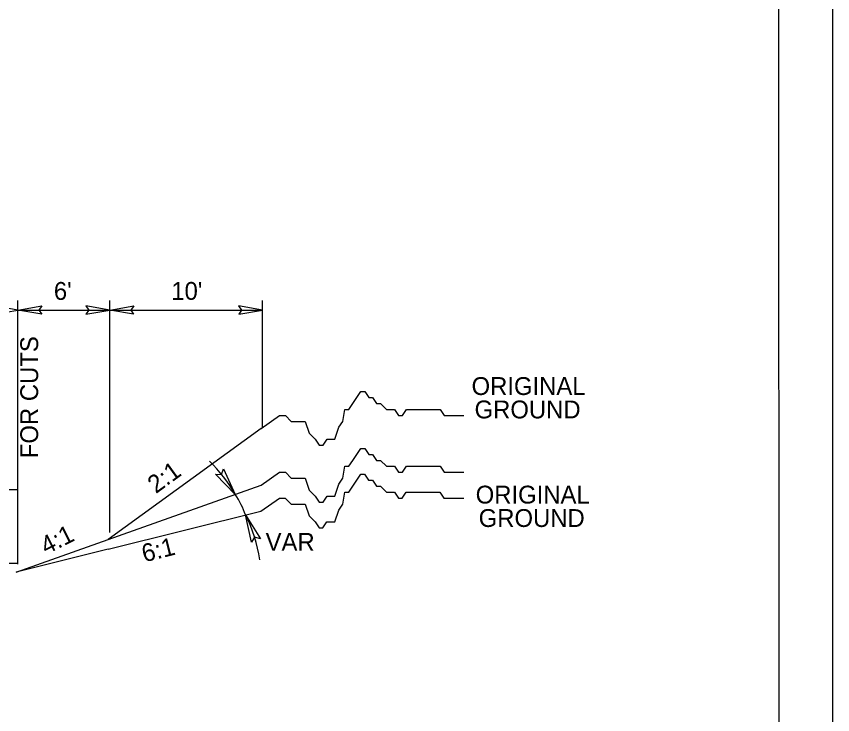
# Model space of a CAD drawing. Extents: x 1725232 to 1728895, y 538685 to 540544.
# Drawn here: x 1725504.7 to 1725568.8, y 539405 to 539459.8 of the extents above; entities that cross this region are included whole.
import ezdxf

# ---------------------------------------------------------------- set-up
doc = ezdxf.new("R2010")
doc.units = 0
for name, color, linetype in [('Default', 7, 'Continuous'), ('Overhead Sheet Border', 7, 'Continuous'), ('Prop Dimension Text', 7, 'Continuous'), ('Scratch_Level_0', 7, 'Continuous'), ('Sheet Plot Border Outside CELL', 7, 'Continuous'), ('Typical Hinge Slope Interstate CELL', 7, 'Continuous'), ('Typical Pavement Slope CELL', 7, 'Continuous')]:
    doc.layers.add(name, color=color, linetype=linetype)

msp = doc.modelspace()

# ---------------------------------------------------------------- linework, layer by layer
at = {"layer": 'Default'}
for p, q in [((1725504.858, 539416.763), (1725504.858, 539437.448)), ((1725512.064, 539419.256), (1725512.064, 539437.448)), ((1725524.073, 539427.519), (1725524.073, 539437.448)), ((1725504.85, 539436.709), (1725512.056, 539436.709)), ((1725512.056, 539436.709), (1725524.066, 539436.709)), ((1725504.858, 539422.604), (1725408.092, 539422.604))]:
    msp.add_line(p, q, dxfattribs=at)
for points in [[(1725502.982, 539436.387), (1725504.858, 539436.71), (1725502.972, 539437.043), (1725503.212, 539436.71)], [(1725506.734, 539436.387), (1725504.858, 539436.71), (1725506.744, 539437.043), (1725506.504, 539436.71)], [(1725510.188, 539436.387), (1725512.064, 539436.71), (1725510.178, 539437.043), (1725510.417, 539436.71)], [(1725513.939, 539436.387), (1725512.064, 539436.71), (1725513.95, 539437.043), (1725513.71, 539436.71)], [(1725522.19, 539436.386), (1725524.066, 539436.709), (1725522.179, 539437.042), (1725522.419, 539436.709)], [(1725521.011, 539424.241), (1725521.92, 539422.244), (1725520.379, 539423.824), (1725520.852, 539423.813)], [(1725523.195, 539418.494), (1725522.729, 539420.637), (1725523.901, 539418.767), (1725523.441, 539418.878)], [(1725523.195, 539418.494), (1725522.729, 539420.637), (1725523.901, 539418.767), (1725523.441, 539418.878)]]:
    msp.add_lwpolyline(points, close=True, dxfattribs=at)
at = {"layer": 'Overhead Sheet Border'}
msp.add_lwpolyline([(1725564.585, 539509.159), (1725264.833, 539508.997), (1725264.945, 539299.171), (1725564.697, 539299.332)], close=True, dxfattribs=at)
at = {"layer": 'Scratch_Level_0'}
msp.add_line((1725501.909, 539416.841), (1725504.858, 539416.841), dxfattribs=at)
at = {"layer": 'Sheet Plot Border Outside CELL'}
msp.add_lwpolyline([(1725568.838, 539514.551), (1725232.256, 539514.551), (1725232.256, 539295.37), (1725568.838, 539295.37)], close=True, dxfattribs=at)
at = {"layer": 'Typical Hinge Slope Interstate CELL'}
for points in [[(1725523.947, 539427.427), (1725525.39, 539428.44), (1725525.858, 539428.44), (1725526.324, 539427.975), (1725526.636, 539427.975), (1725527.104, 539427.975), (1725527.415, 539427.975), (1725527.727, 539427.037), (1725528.194, 539426.571), (1725528.506, 539426.102), (1725528.817, 539426.102), (1725529.129, 539426.571), (1725529.44, 539426.571), (1725529.752, 539426.571), (1725530.063, 539427.506), (1725530.375, 539427.975), (1725530.531, 539428.909), (1725530.842, 539428.909), (1725531.154, 539429.374), (1725531.465, 539429.843), (1725531.777, 539430.313), (1725532.088, 539430.313), (1725532.4, 539429.843), (1725532.711, 539429.843), (1725533.022, 539429.374), (1725533.334, 539429.374), (1725533.802, 539428.909), (1725534.113, 539428.909), (1725534.425, 539428.909), (1725534.736, 539428.44), (1725535.047, 539428.44), (1725535.359, 539428.909), (1725535.67, 539428.909), (1725535.982, 539428.909), (1725536.293, 539428.909), (1725536.605, 539428.909), (1725537.072, 539428.909), (1725537.539, 539428.909), (1725538.007, 539428.909), (1725538.318, 539428.44), (1725538.785, 539428.44), (1725539.253, 539428.44), (1725539.875, 539428.44)], [(1725523.947, 539422.964), (1725525.39, 539423.978), (1725525.858, 539423.978), (1725526.324, 539423.512), (1725526.636, 539423.512), (1725527.104, 539423.512), (1725527.415, 539423.512), (1725527.727, 539422.574), (1725528.194, 539422.109), (1725528.506, 539421.64), (1725528.817, 539421.64), (1725529.129, 539422.109), (1725529.44, 539422.109), (1725529.752, 539422.109), (1725530.063, 539423.043), (1725530.375, 539423.512), (1725530.531, 539424.447), (1725530.842, 539424.447), (1725531.154, 539424.912), (1725531.465, 539425.381), (1725531.777, 539425.85), (1725532.088, 539425.85), (1725532.4, 539425.381), (1725532.711, 539425.381), (1725533.022, 539424.912), (1725533.334, 539424.912), (1725533.802, 539424.447), (1725534.113, 539424.447), (1725534.425, 539424.447), (1725534.736, 539423.978), (1725535.047, 539423.978), (1725535.359, 539424.447), (1725535.67, 539424.447), (1725535.982, 539424.447), (1725536.293, 539424.447), (1725536.605, 539424.447), (1725537.072, 539424.447), (1725537.539, 539424.447), (1725538.007, 539424.447), (1725538.318, 539423.978), (1725538.785, 539423.978), (1725539.253, 539423.978), (1725539.875, 539423.978)], [(1725523.94, 539420.94), (1725525.384, 539421.953), (1725525.851, 539421.953), (1725526.318, 539421.488), (1725526.629, 539421.488), (1725527.097, 539421.488), (1725527.409, 539421.488), (1725527.72, 539420.55), (1725528.188, 539420.084), (1725528.499, 539419.615), (1725528.811, 539419.615), (1725529.122, 539420.084), (1725529.434, 539420.084), (1725529.745, 539420.084), (1725530.057, 539421.019), (1725530.368, 539421.488), (1725530.524, 539422.422), (1725530.836, 539422.422), (1725531.147, 539422.887), (1725531.459, 539423.357), (1725531.77, 539423.826), (1725532.082, 539423.826), (1725532.393, 539423.357), (1725532.704, 539423.357), (1725533.016, 539422.887), (1725533.327, 539422.887), (1725533.795, 539422.422), (1725534.107, 539422.422), (1725534.418, 539422.422), (1725534.729, 539421.953), (1725535.041, 539421.953), (1725535.352, 539422.422), (1725535.664, 539422.422), (1725535.975, 539422.422), (1725536.287, 539422.422), (1725536.598, 539422.422), (1725537.066, 539422.422), (1725537.532, 539422.422), (1725538, 539422.422), (1725538.312, 539421.953), (1725538.778, 539421.953), (1725539.246, 539421.953), (1725539.869, 539421.953)]]:
    msp.add_lwpolyline(points, dxfattribs=at)
for centre, start, end in [((1725511.441, 539416.254), 29.75191, 45.50364), ((1725511.933, 539415.238), 8.9538, 26.57006), ((1725511.933, 539415.238), 8.9538, 26.57006)]:
    msp.add_arc(centre, 12.071, start, end, dxfattribs=at)
msp.add_ellipse((1725511.823, 539422.851), major_axis=(10.894, -5.199), ratio=0.5, start_param=0.463735, end_param=0.681536, dxfattribs=at)
at = {"layer": 'Typical Pavement Slope CELL'}
for p, q in [((1725523.947, 539427.427), (1725511.952, 539418.703)), ((1725504.728, 539416.136), (1725523.947, 539422.964)), ((1725511.933, 539417.937), (1725523.94, 539420.94)), ((1725511.933, 539417.937), (1725504.728, 539416.136))]:
    msp.add_line(p, q, dxfattribs=at)

# ---------------------------------------------------------------- texts
at = {"layer": 'Prop Dimension Text'}
for s, p in [("6'", (1725507.677, 539437.509)), ("10'", (1725516.898, 539437.509)), ('ORIGINAL', (1725540.479, 539430.044)), ('GROUND', (1725540.714, 539428.208)), ('ORIGINAL', (1725540.803, 539421.526)), ('GROUND', (1725541.039, 539419.689)), ('VAR', (1725524.306, 539417.816))]:
    msp.add_text(s, height=1.4011, dxfattribs=at).set_placement(p)
for s, rotation, p in [('FOR CUTS', 90, (1725506.441, 539425.082)), ('2:1', 36.02984, (1725515.688, 539422.262)), ('4:1', 26.57006, (1725507.073, 539417.494)), ('6:1', 14.03809, (1725514.774, 539416.906))]:
    msp.add_text(s, height=1.4011, rotation=rotation, dxfattribs=at).set_placement(p)

doc.saveas('drawing.dxf')
